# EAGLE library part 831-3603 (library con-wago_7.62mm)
Serie 831, Stiftleiste (für Leiterplatten) mit geraden Einlötstiften / Series 831, Male header (for PCBs) with straight solder pins Polzahl / Pole No.: 3 Bemessungsspannung / Rated Voltage: 630 V Nennstrom / Nominal Current: 41 A Lötstiftlänge: / Solder Pin Length: 4 mm Farbe / Color: lichtgrau / light gray Stand: 01.01.2012. Die jeweils aktuellen Daten zu diesem Artikel finden Sie in unserem Produktkatalog, den Sie unter www.wago.com einsehen können. As of: 01/01/2012. Please find the newest data for this article in our product catalogue, which can be viewed under www.wago.com.
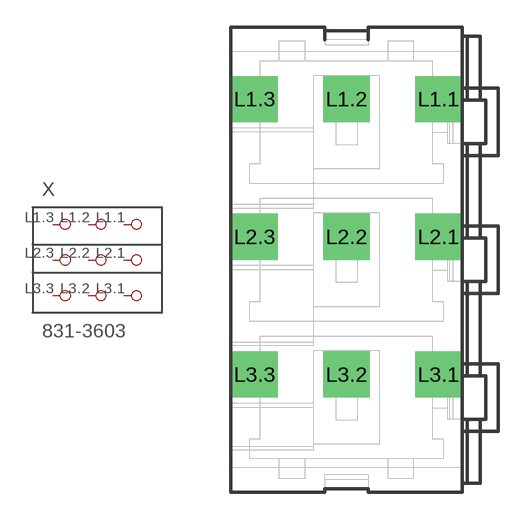
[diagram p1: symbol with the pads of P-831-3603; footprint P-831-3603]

Designator prefix X

## 831-3603  [P-831-3603]
L1.1  P1.1
L1.2  P1.2
L1.3  P1.3
L2.1  P2.1
L2.2  P2.2
L2.3  P2.3
L3.1  P3.1
L3.2  P3.2
L3.3  P3.3

## Footprint P-831-3603 (pad centres in mm)
drill 1.7 square: L1.1 4.08,8.89; L1.2 -1,8.89; L1.3 -6.08,8.89; L2.1 4.08,1.27; L2.2 -1,1.27; L2.3 -6.08,1.27; L3.1 4.08,-6.35; L3.2 -1,-6.35; L3.3 -6.08,-6.35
